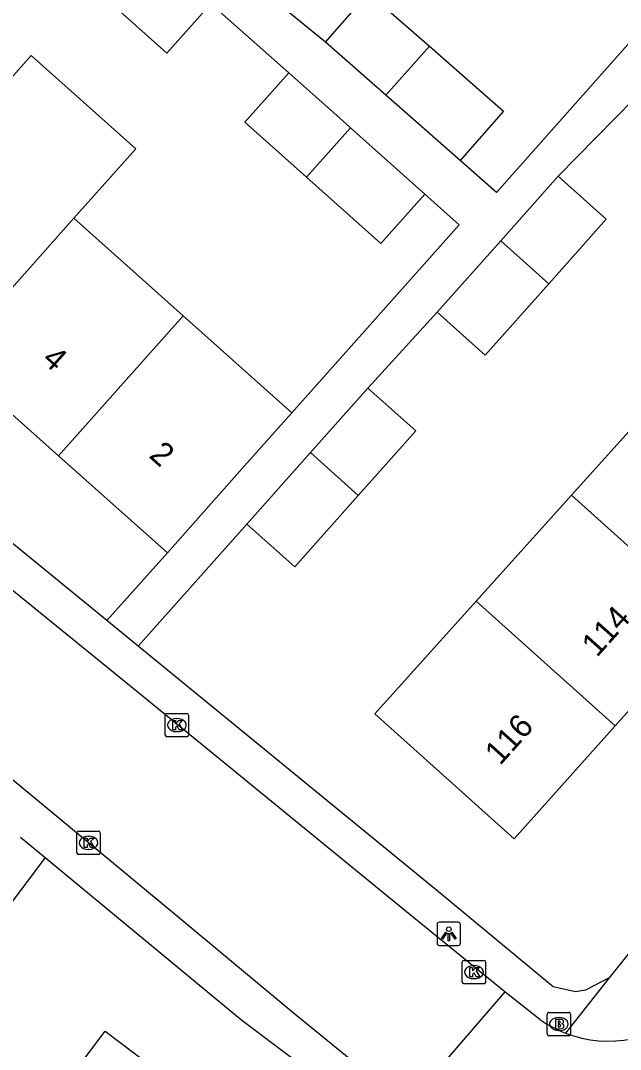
# Model space of a CAD drawing. Extents: x 159040 to 160094, y 381214 to 382518.
# Drawn here: x 159473.17 to 159498.85, y 381951.1 to 381995.12 of the extents above; entities that cross this region are included whole.
import ezdxf

# ---------------------------------------------------------------- set-up
doc = ezdxf.new("R2010")
doc.units = 0
for name, color, linetype in [('IMGEO_Brandkraan', 7, 'Continuous'), ('IMGEO_Kolk', 7, 'Continuous'), ('IMGEO_Lichtpunt', 7, 'Continuous'), ('IMGEO_Pand', 7, 'Continuous'), ('IMGEO_Pand_nummerreeks', 7, 'Continuous'), ('IMGEO_Rijbaan_lokaal_gesloten', 7, 'Continuous'), ('IMGEO_Rijbaan_lokaal_open', 7, 'Continuous'), ('IMGEO_Voetpad_open', 7, 'Continuous')]:
    doc.layers.add(name, color=color, linetype=linetype)

msp = doc.modelspace()

# ---------------------------------------------------------------- linework, layer by layer
at = {"layer": 'IMGEO_Brandkraan'}
for p, q in [((159495.794, 381952.684), (159496.646, 381952.684)), ((159495.719, 381951.758), (159495.719, 381952.61)), ((159496.207, 381952.464), (159496.232, 381952.464)), ((159496.72, 381952.61), (159496.72, 381951.758)), ((159496.23, 381951.904), (159496.205, 381951.904)), ((159496.646, 381951.684), (159495.794, 381951.684))]:
    msp.add_line(p, q, dxfattribs=at)
for points in [[(159495.794, 381952.684), (159496.646, 381952.684)], [(159495.719, 381951.758), (159495.719, 381952.61)], [(159496.067, 381952.384), (159496.067, 381951.984), (159496.28, 381951.984)], [(159496.298, 381952.384), (159496.067, 381952.384)], [(159496.246, 381952.303), (159496.192, 381952.303), (159496.192, 381952.227)], [(159496.192, 381952.227), (159496.245, 381952.227)], [(159496.72, 381952.61), (159496.72, 381951.758)], [(159496.254, 381952.151), (159496.192, 381952.151), (159496.192, 381952.07)], [(159496.192, 381952.07), (159496.254, 381952.07)], [(159496.646, 381951.684), (159495.794, 381951.684)]]:
    msp.add_lwpolyline(points, dxfattribs=at)
for centre, radius, start, end in [((159495.796, 381952.608), 0.0765, 91.552, 178.448), ((159495.796, 381952.608), 0.0765, 91.552, 178.448), ((159496.644, 381952.608), 0.0765, 1.552, 88.448), ((159496.644, 381952.608), 0.0765, 1.552, 88.448), ((159496.247, 381952.265), 0.0379, 267.8285, 90.9355), ((159496.302, 381952.239), 0.145, 59.4692, 91.5367), ((159496.327, 381952.286), 0.0922, 285.5137, 58.1501), ((159496.255, 381952.11), 0.0404, 269.8759, 90.5077), ((159496.286, 381952.235), 0.251, 268.6676, 293.5347), ((159496.332, 381952.094), 0.105, 301.3115, 78.989), ((159495.796, 381951.76), 0.0765, 181.552, 268.448), ((159495.796, 381951.76), 0.0765, 181.552, 268.448), ((159496.644, 381951.76), 0.0765, 271.552, 358.448), ((159496.644, 381951.76), 0.0765, 271.552, 358.448)]:
    msp.add_arc(centre, radius, start, end, dxfattribs=at)
for centre, major_axis, ratio, start_param, end_param in [((159496.206, 381952.184), (-0.387, 0.002), 0.722429, 4.712389, 7.853982), ((159496.231, 381952.184), (-0.39, 0.002), 0.717154, 1.570796, 4.712389)]:
    msp.add_ellipse(centre, major_axis=major_axis, ratio=ratio, start_param=start_param, end_param=end_param, dxfattribs=at)
at = {"layer": 'IMGEO_Kolk'}
for p, q in [((159479.437, 381965.478), (159480.289, 381965.478)), ((159479.362, 381964.552), (159479.362, 381965.404)), ((159479.85, 381965.258), (159479.875, 381965.258)), ((159480.363, 381965.404), (159480.363, 381964.552)), ((159479.873, 381964.698), (159479.848, 381964.698)), ((159480.289, 381964.478), (159479.437, 381964.478)), ((159475.575, 381959.513), (159475.575, 381960.365)), ((159475.65, 381960.439), (159476.502, 381960.439)), ((159476.063, 381960.219), (159476.088, 381960.219)), ((159476.576, 381960.365), (159476.576, 381959.513)), ((159476.502, 381959.439), (159475.65, 381959.439)), ((159476.086, 381959.659), (159476.061, 381959.659)), ((159492.157, 381954.906), (159493.009, 381954.906)), ((159492.082, 381953.98), (159492.082, 381954.832)), ((159492.57, 381954.686), (159492.595, 381954.686)), ((159493.083, 381954.832), (159493.083, 381953.98)), ((159492.593, 381954.126), (159492.568, 381954.126)), ((159493.009, 381953.906), (159492.157, 381953.906))]:
    msp.add_line(p, q, dxfattribs=at)
for points in [[(159479.437, 381965.478), (159480.289, 381965.478)], [(159479.362, 381964.552), (159479.362, 381965.404)], [(159479.683, 381965.178), (159479.806, 381965.178), (159479.806, 381965.027), (159479.936, 381965.178), (159480.1, 381965.178), (159479.954, 381965.027), (159480.107, 381964.778), (159479.955, 381964.778), (159479.87, 381964.942), (159479.806, 381964.875), (159479.806, 381964.778), (159479.683, 381964.778), (159479.683, 381965.178)], [(159480.363, 381965.404), (159480.363, 381964.552)], [(159480.289, 381964.478), (159479.437, 381964.478)], [(159475.575, 381959.513), (159475.575, 381960.365)], [(159475.65, 381960.439), (159476.502, 381960.439)], [(159476.576, 381960.365), (159476.576, 381959.513)], [(159475.896, 381960.139), (159476.019, 381960.139), (159476.019, 381959.988), (159476.149, 381960.139), (159476.313, 381960.139), (159476.167, 381959.988), (159476.32, 381959.739), (159476.168, 381959.739), (159476.083, 381959.903), (159476.019, 381959.836), (159476.019, 381959.739), (159475.896, 381959.739), (159475.896, 381960.139)], [(159476.502, 381959.439), (159475.65, 381959.439)], [(159492.157, 381954.906), (159493.009, 381954.906)], [(159492.082, 381953.98), (159492.082, 381954.832)], [(159492.403, 381954.606), (159492.526, 381954.606), (159492.526, 381954.455), (159492.656, 381954.606), (159492.82, 381954.606), (159492.674, 381954.455), (159492.827, 381954.206), (159492.675, 381954.206), (159492.59, 381954.37), (159492.526, 381954.303), (159492.526, 381954.206), (159492.403, 381954.206), (159492.403, 381954.606)], [(159493.083, 381954.832), (159493.083, 381953.98)], [(159493.009, 381953.906), (159492.157, 381953.906)]]:
    msp.add_lwpolyline(points, dxfattribs=at)
for centre, start, end in [((159479.439, 381965.402), 91.552, 178.448), ((159479.439, 381965.402), 91.552, 178.448), ((159480.287, 381965.402), 1.552, 88.448), ((159480.287, 381965.402), 1.552, 88.448), ((159479.439, 381964.554), 181.552, 268.448), ((159479.439, 381964.554), 181.552, 268.448), ((159480.287, 381964.554), 271.552, 358.448), ((159480.287, 381964.554), 271.552, 358.448), ((159475.652, 381960.363), 91.552, 178.448), ((159475.652, 381960.363), 91.552, 178.448), ((159476.5, 381960.363), 1.552, 88.448), ((159476.5, 381960.363), 1.552, 88.448), ((159475.652, 381959.515), 181.552, 268.448), ((159475.652, 381959.515), 181.552, 268.448), ((159476.5, 381959.515), 271.552, 358.448), ((159476.5, 381959.515), 271.552, 358.448), ((159492.159, 381954.83), 91.552, 178.448), ((159492.159, 381954.83), 91.552, 178.448), ((159493.007, 381954.83), 1.552, 88.448), ((159493.007, 381954.83), 1.552, 88.448), ((159492.159, 381953.982), 181.552, 268.448), ((159492.159, 381953.982), 181.552, 268.448), ((159493.007, 381953.982), 271.552, 358.448), ((159493.007, 381953.982), 271.552, 358.448)]:
    msp.add_arc(centre, 0.0765, start, end, dxfattribs=at)
for centre, major_axis, ratio, start_param, end_param in [((159479.849, 381964.978), (-0.387, 0.002), 0.722429, 4.712389, 7.853982), ((159479.874, 381964.978), (-0.39, 0.002), 0.717154, 1.570796, 4.712389), ((159476.062, 381959.939), (-0.387, 0.002), 0.722429, 4.712389, 7.853982), ((159476.087, 381959.939), (-0.39, 0.002), 0.717154, 1.570796, 4.712389), ((159492.569, 381954.406), (-0.387, 0.002), 0.722429, 4.712389, 7.853982), ((159492.594, 381954.406), (-0.39, 0.002), 0.717154, 1.570796, 4.712389)]:
    msp.add_ellipse(centre, major_axis=major_axis, ratio=ratio, start_param=start_param, end_param=end_param, dxfattribs=at)
at = {"layer": 'IMGEO_Lichtpunt'}
for p, q in [((159491.006, 381956.446), (159491.006, 381955.639)), ((159491.006, 381956.446), (159491.006, 381955.639)), ((159491.908, 381956.541), (159491.1, 381956.541)), ((159491.908, 381956.541), (159491.1, 381956.541)), ((159492.002, 381955.639), (159492.002, 381956.446)), ((159492.002, 381955.639), (159492.002, 381956.446)), ((159491.1, 381955.545), (159491.908, 381955.545)), ((159491.1, 381955.545), (159491.908, 381955.545))]:
    msp.add_line(p, q, dxfattribs=at)
for points in [[(159491.38, 381956.11), (159491.419, 381956.082), (159491.231, 381955.82), (159491.193, 381955.847), (159491.38, 381956.11)], [(159491.482, 381956.062), (159491.529, 381956.062), (159491.529, 381955.74), (159491.482, 381955.74), (159491.482, 381956.062)], [(159491.592, 381956.082), (159491.63, 381956.109), (159491.817, 381955.847), (159491.778, 381955.819), (159491.592, 381956.082)]]:
    msp.add_lwpolyline(points, dxfattribs=at)
msp.add_circle((159491.505, 381956.244), 0.0994, dxfattribs=at)
for centre, start, end in [((159491.1, 381956.446), 90, 180), ((159491.1, 381956.446), 90, 180), ((159491.908, 381956.446), 0, 90), ((159491.908, 381956.446), 0, 90), ((159491.1, 381955.639), 180, 270), ((159491.1, 381955.639), 180, 270), ((159491.908, 381955.639), 270, 0), ((159491.908, 381955.639), 270, 360)]:
    msp.add_arc(centre, 0.0946, start, end, dxfattribs=at)
at = {"layer": 'IMGEO_Pand'}
for points in [[(159481.32, 381995.844), (159479.436, 381993.733), (159476.249, 381996.578)], [(159486.22, 381994.204), (159488.073, 381996.315), (159490.682, 381994.025)], [(159488.806, 381991.935), (159486.22, 381994.204)], [(159470.978, 381990.659), (159473.623, 381993.624), (159478.097, 381989.633), (159475.452, 381986.668)], [(159488.806, 381991.935), (159490.682, 381994.025)], [(159490.682, 381994.025), (159493.842, 381991.252), (159491.989, 381989.142)], [(159485.41, 381988.423), (159482.775, 381990.775), (159484.659, 381992.886)], [(159484.659, 381992.886), (159486.963, 381990.829), (159487.291, 381990.536)], [(159491.989, 381989.142), (159488.806, 381991.935)], [(159485.41, 381988.423), (159487.291, 381990.536)], [(159487.291, 381990.536), (159490.48, 381987.69)], [(159490.48, 381987.69), (159488.596, 381985.579), (159485.41, 381988.423)], [(159493.735, 381985.704), (159496.189, 381988.46)], [(159496.189, 381988.46), (159498.247, 381986.628), (159495.786, 381983.865)], [(159470.11, 381980.669), (159475.452, 381986.668)], [(159475.452, 381986.668), (159480.13, 381982.495)], [(159491.007, 381982.641), (159493.735, 381985.704)], [(159493.735, 381985.704), (159495.786, 381983.865)], [(159495.786, 381983.865), (159493.065, 381980.809), (159491.007, 381982.641)], [(159480.13, 381982.495), (159474.792, 381976.501)], [(159480.13, 381982.495), (159484.786, 381978.343)], [(159474.792, 381976.501), (159470.11, 381980.669)], [(159485.579, 381976.643), (159488.033, 381979.399)], [(159488.033, 381979.399), (159490.091, 381977.567), (159487.63, 381974.804)], [(159496.762, 381974.815), (159500, 381978.413), (159500.834, 381979.339)], [(159484.786, 381978.343), (159482.758, 381976.065), (159479.452, 381972.353)], [(159479.452, 381972.353), (159474.792, 381976.501)], [(159482.851, 381973.58), (159485.579, 381976.643)], [(159485.579, 381976.643), (159487.63, 381974.804)], [(159487.63, 381974.804), (159484.909, 381971.748), (159482.851, 381973.58)], [(159492.678, 381970.278), (159496.762, 381974.815)], [(159496.762, 381974.815), (159500, 381971.912), (159502.704, 381969.488)], [(159498.629, 381964.942), (159494.301, 381960.113), (159488.337, 381965.455), (159492.678, 381970.278)], [(159498.629, 381964.942), (159492.678, 381970.278)], [(159502.704, 381969.488), (159500, 381966.471), (159498.629, 381964.942)], [(159475.39, 381944.892), (159475.626, 381945.207), (159473.168, 381947.054), (159476.791, 381951.875), (159479.249, 381950.027), (159486.026, 381944.933), (159482.167, 381939.798)]]:
    msp.add_lwpolyline(points, dxfattribs=at)
at = {"layer": 'IMGEO_Rijbaan_lokaal_gesloten'}
for points in [[(159493.902, 381953.566), (159489.71, 381948.693)], [(159495.4, 381952.384), (159493.902, 381953.566)]]:
    msp.add_lwpolyline(points, dxfattribs=at)
for centre, radius, start, end in [((159498.349, 381956.586), 5.134, 248.8673, 313.6177), ((159498.342, 381956.567), 5.114, 234.8791, 248.8622)]:
    msp.add_arc(centre, radius, start, end, dxfattribs=at)
at = {"layer": 'IMGEO_Rijbaan_lokaal_open'}
for points in [[(159493.902, 381953.566), (159490.011, 381956.729), (159478.439, 381966.173), (159470.716, 381972.439), (159465.366, 381976.894), (159453.588, 381986.5), (159445.068, 381993.5), (159438.342, 381999.131), (159437.228, 382000), (159436.96, 382000.209), (159433.343, 382003.032), (159431.111, 382004.883), (159430.938, 382005.027), (159428.686, 382006.888), (159423.484, 382011.193), (159418.831, 382015.025), (159418.213, 382015.458)], [(159489.71, 381948.693), (159484.836, 381952.668), (159479.726, 381956.917), (159471.127, 381964.038), (159463.814, 381970.062), (159459.269, 381973.743), (159451.637, 381979.96), (159448.636, 381982.36), (159445.379, 381985.069), (159444.352, 381985.904), (159443.914, 381986.206), (159442.88, 381987.591), (159441.923, 381988.326)]]:
    msp.add_lwpolyline(points, dxfattribs=at)
at = {"layer": 'IMGEO_Voetpad_open'}
for points in [[(159476.864, 381969.447), (159440.692, 381999.01), (159440.063, 382000)], [(159486.22, 381994.204), (159482.484, 381997.247)], [(159481.32, 381995.844), (159484.659, 381992.886)], [(159500.516, 381995.608), (159493.548, 381987.774), (159491.989, 381989.142)], [(159496.189, 381988.46), (159499.436, 381991.78)], [(159490.48, 381987.69), (159491.944, 381986.383), (159484.786, 381978.343)], [(159488.033, 381979.399), (159491.007, 381982.641)], [(159521.684, 381982.888), (159514.006, 381973.671), (159498.368, 381954.162)], [(159478.198, 381968.356), (159482.851, 381973.58)], [(159479.452, 381972.353), (159476.864, 381969.447)], [(159478.198, 381968.356), (159476.864, 381969.447)], [(159498.368, 381954.162), (159497.363, 381953.636), (159496.934, 381953.563), (159495.967, 381953.779), (159491.064, 381957.84), (159478.198, 381968.356)], [(159473.165, 381960.187), (159474.224, 381959.31)], [(159474.224, 381959.31), (159470.073, 381953.789)], [(159474.224, 381959.31), (159482.645, 381952.343), (159486.209, 381949.671), (159490.205, 381946.373), (159490.624, 381945.41), (159490.602, 381944.349), (159490.312, 381943.7)], [(159498.368, 381954.162), (159496.498, 381951.797)]]:
    msp.add_lwpolyline(points, dxfattribs=at)

# ---------------------------------------------------------------- texts
at = {"layer": 'IMGEO_Pand_nummerreeks'}
for s, rotation, p in [('4', 318.3136, (159474.037, 381980.551)), ('2', 318.3136, (159478.626, 381976.464)), ('114', 48.1269, (159497.85, 381967.847)), ('116', 48.1269, (159493.701, 381963.219))]:
    msp.add_text(s, height=1, rotation=rotation, dxfattribs=at).set_placement(p)

doc.saveas('drawing.dxf')
